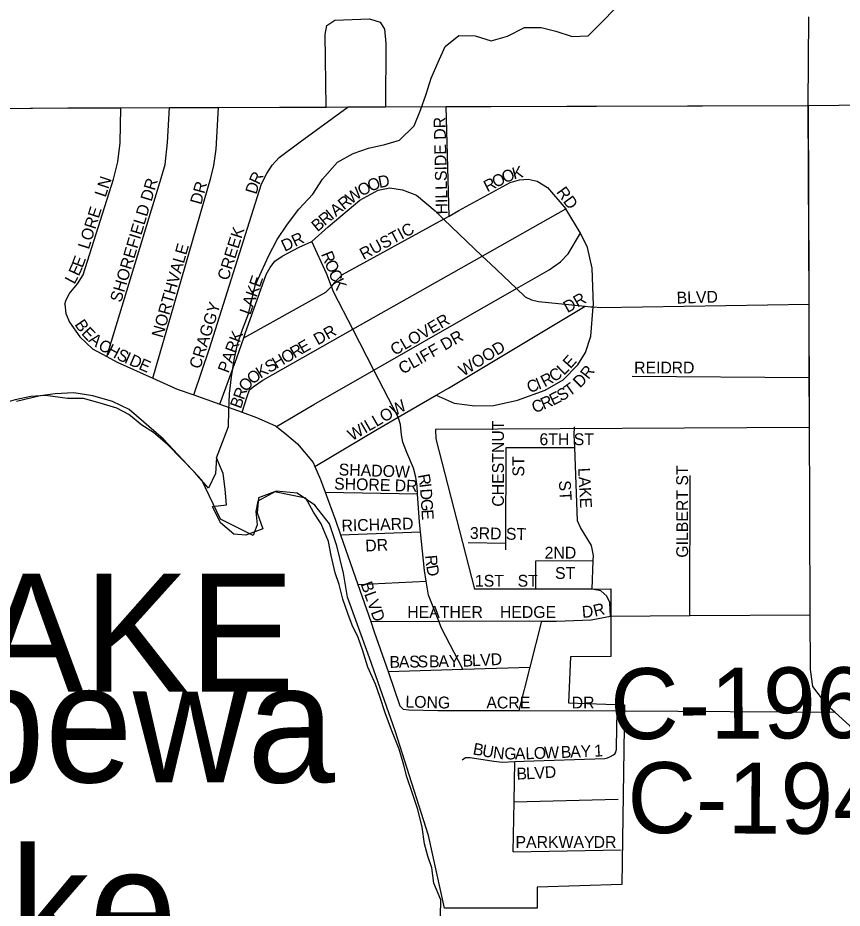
# Model space of a CAD drawing. Extents: x 1985906 to 2277390, y 930619 to 1324581.
# Drawn here: x 2131073 to 2134559, y 1117937 to 1121701 of the extents above; entities that cross this region are included whole.
import ezdxf

# ---------------------------------------------------------------- set-up
doc = ezdxf.new("R2010")
doc.units = 0
for name, color, linetype in [('GM_X_City_Street', 7, 'Continuous'), ('GM_X_City_Street_Text', 7, 'Continuous'), ('GM_X_Corporation', 7, 'Continuous'), ('GM_X_Corporation_Text', 7, 'Continuous'), ('GM_X_County_Road', 7, 'Continuous'), ('GM_X_County_Road_Text', 7, 'Continuous'), ('GM_X_Major_Lake', 7, 'Continuous'), ('GM_X_Major_Lake_Text', 7, 'Continuous'), ('GM_X_Minor_River', 7, 'Continuous'), ('GM_X_Township_Road', 7, 'Continuous'), ('GM_X_Township_Subdivision', 7, 'Continuous'), ('GM_X_Township_Subdivision_Text', 7, 'Continuous')]:
    doc.layers.add(name, color=color, linetype=linetype)

msp = doc.modelspace()

# ---------------------------------------------------------------- linework, layer by layer
at = {"layer": 'GM_X_City_Street'}
for points in [[(2131272.5, 1120490.7), (2131276.6, 1120504.7), (2131290.8, 1120534.7), (2131325.1, 1120576.5), (2131349.3, 1120614.5), (2131477.5, 1121018.5), (2131495.9, 1121092.5), (2131506.3, 1121172.6), (2131509.1, 1121320.9)], [(2131449.3, 1120269.1), (2131683.8, 1121037.3), (2131696.1, 1121081.3), (2131706.6, 1121173.4), (2131715.3, 1121321.6)], [(2131644.4, 1120177.4), (2131890, 1121024.1), (2131902.2, 1121076.1), (2131912.6, 1121146.2), (2131921.6, 1121322.3)], [(2131817.2, 1120107), (2131884.2, 1120302.8), (2132104.1, 1120998.8), (2132126.3, 1121042.7), (2132148.5, 1121078.7), (2132178.7, 1121110.6), (2132267.2, 1121176.2), (2132470.1, 1121324.1)], [(2132896.7, 1120862.9), (2132884.5, 1121325.4)], [(2132028.4, 1120347.5), (2132376, 1120540.4), (2132400.3, 1120565.1), (2132420.2, 1120590.2), (2132446.4, 1120616.1), (2132873.7, 1120850.3), (2132896.7, 1120862.9), (2132938.3, 1120885.8), (2133155.1, 1121004.7), (2133195.3, 1121016.5), (2133231.3, 1121018.3), (2133269.3, 1121010.1), (2133313.2, 1120983.8), (2133390.8, 1120893.2)], [(2132317, 1120755.1), (2132385.4, 1120816.9), (2132520.1, 1120930.3), (2132596.4, 1120971.9), (2132646.5, 1120981.6), (2132700.5, 1120973.3), (2132758.5, 1120950.9), (2132838.2, 1120884.3), (2132873.7, 1120850.3), (2133037.2, 1120693.3), (2133071.3, 1120660.6), (2133181.8, 1120556.3), (2133218.7, 1120521.5), (2133244.7, 1120509.3), (2133274.6, 1120501.1), (2133472.8, 1120481.9), (2133496.4, 1120479.7)], [(2132021.6, 1120033.4), (2132042.5, 1120100.3), (2132053.3, 1120127.8), (2132068.1, 1120140.7), (2132109.7, 1120169.3), (2132490.1, 1120384.2), (2133037.2, 1120693.3), (2133390.8, 1120893.2)], [(2132167.4, 1119972.9), (2132325.4, 1120065.9), (2132579, 1120211.1), (2133181.8, 1120556.3), (2133319.4, 1120635.1), (2133367.6, 1120668.9), (2133399.8, 1120702.8), (2133452.4, 1120790.6), (2133390.8, 1120893.2)], [(2133155.2, 1120077.7), (2133155.7, 1120077.9), (2133186.4, 1120084.9), (2133302.8, 1120126.3), (2133379, 1120169.9), (2133441.4, 1120233.7), (2133473.8, 1120285.6), (2133496.1, 1120355.6), (2133506.2, 1120478.7), (2133506.8, 1120485.8), (2133501.6, 1120642.1), (2133482.1, 1120730.3), (2133452.4, 1120790.6)], [(2131927.5, 1120067.6), (2132000.1, 1120264.1), (2132028.4, 1120347.5), (2132034.7, 1120366.1), (2132124.1, 1120616), (2132140.3, 1120646), (2132160.4, 1120671.9), (2132190.6, 1120693.8), (2132262.8, 1120731.4), (2132317, 1120755.1)], [(2132954.6, 1118946.9), (2132865.1, 1119121.1), (2132853.7, 1119149.6), (2132809.7, 1119259.7), (2132799.8, 1119318.8), (2132792.3, 1119363.9), (2132775.4, 1119528.3), (2132771.3, 1119568.4), (2132764, 1119689.1), (2132762.1, 1119720.7), (2132756.3, 1119758.8), (2132746.5, 1119796.9), (2132718.8, 1119863.2), (2132701, 1119907.4), (2132695.1, 1119937.5), (2132691.3, 1119981.6), (2132683.5, 1120007.7), (2132681.2, 1120012.2), (2132579, 1120211.1), (2132490.1, 1120384.2), (2132410, 1120540.2), (2132400.3, 1120565.1), (2132380.3, 1120616.5), (2132317, 1120755.1)], [(2131272.5, 1120490.7), (2131276.3, 1120450.6), (2131292.2, 1120414.5), (2131335.9, 1120352.1), (2131389.7, 1120301.7), (2131449.3, 1120269.1), (2131493.5, 1120245), (2131644.4, 1120177.4), (2131747.2, 1120131.3), (2131817.2, 1120107), (2131853.1, 1120094.6), (2131927.5, 1120067.6), (2132021.6, 1120033.4), (2132082.9, 1120011.1), (2132162.8, 1119976.6), (2132167.4, 1119972.9), (2132210.6, 1119938.3), (2132256.5, 1119900), (2132322.1, 1119821.4), (2132329.7, 1119804.1), (2132353.8, 1119749.1), (2132373.2, 1119696.1), (2132417, 1119576.5), (2132438.2, 1119515.4), (2132511.3, 1119304.6), (2132565.5, 1119148.5), (2132580.7, 1119104.7), (2132638.6, 1118937.6), (2132689.2, 1118791.6), (2132703.1, 1118777.5)], [(2132329.7, 1119804.1), (2132587.1, 1119958.2), (2132681.2, 1120012.2), (2132842.9, 1120105.1), (2132894.4, 1120134.7), (2133472.8, 1120481.9)], [(2133496.4, 1120479.7), (2133497.4, 1120479.6), (2133506.2, 1120478.7), (2133538.8, 1120475.6), (2134418.7, 1120490.6)], [(2133671.4, 1120186.3), (2134420, 1120180)], [(2132842.9, 1120105.1), (2132918.1, 1120072.5), (2133006.1, 1120059.9), (2133084.2, 1120061.5), (2133155.2, 1120077.7)], [(2132373.2, 1119696.1), (2132764, 1119689.1)], [(2132438.2, 1119515.4), (2132775.4, 1119528.3)], [(2132511.3, 1119304.6), (2132799.8, 1119318.8)], [(2132565.5, 1119148.5), (2132853.7, 1119149.6), (2133237.6, 1119151), (2133289.6, 1119150.7), (2133351.7, 1119150.4), (2133497.9, 1119155.5), (2133579.7, 1119171.8)], [(2133193.6, 1118771.9), (2133240.1, 1118955.3), (2133289.6, 1119150.7)], [(2132638.6, 1118937.6), (2132954.6, 1118946.9), (2133240.1, 1118955.3)], [(2132703.1, 1118777.5), (2132727.1, 1118775.3), (2132849.2, 1118772.6), (2133193.6, 1118771.9), (2133608, 1118771), (2133642.7, 1118770.9)], [(2132952.3, 1118563.6), (2132966.3, 1118573.6), (2132986.4, 1118573.5), (2133086.4, 1118558.9), (2133122.4, 1118554.7), (2133174.3, 1118556.7), (2133212.5, 1118558.1), (2133554.9, 1118570.2), (2133566.9, 1118572.4), (2133579, 1118578.1), (2133592, 1118585.1), (2133597.9, 1118589.8), (2133601.1, 1118594), (2133604.1, 1118607.2), (2133605.2, 1118618), (2133608, 1118771)], [(2133168.5, 1118175.7), (2133171.7, 1118386.1), (2133174.3, 1118556.7)], [(2133171.7, 1118386.1), (2133612.1, 1118397.6)], [(2133168.5, 1118175.7), (2133625, 1118183.1)]]:
    msp.add_lwpolyline(points, dxfattribs=at)
at = {"layer": 'GM_X_Corporation'}
msp.add_lwpolyline([(2130535, 1121313.6), (2131284.7, 1121320.1), (2134415.5, 1121330.5), (2134417.8, 1120570.3), (2134419.8, 1119968.9), (2132838.9, 1119960.6), (2132841.1, 1119920.6), (2133004.7, 1119286), (2133580.8, 1119287.5), (2133580.5, 1119001.3), (2133410.2, 1118998.9), (2133402.1, 1118804.5), (2133638.6, 1118796.9), (2133627.2, 1118036.3), (2133268.8, 1118025.3), (2133269.1, 1117937.2), (2132877, 1117937.3), (2132810, 1118244.2), (2132668.4, 1118687.2), (2132559.7, 1118994.8), (2132468, 1119251), (2132450, 1119353.1), (2132422.4, 1119468.5), (2132391.9, 1119561.7), (2132328.9, 1119640.9), (2132254.7, 1119691.4), (2132166.1, 1119699.9), (2132088.9, 1119657.3), (2132080, 1119614.1), (2132084.8, 1119556.8), (2132068.9, 1119512.9), (2131929.8, 1119581.8), (2131850.9, 1119746.1), (2131689.1, 1119920.1), (2131544.5, 1120044.8), (2131473.4, 1120078.2), (2131389.9, 1120103.3), (2131310.5, 1120115.9), (2131231.1, 1120111.7), (2131168.5, 1120103.4), (2131068.2, 1120078.3)], dxfattribs=at)
at = {"layer": 'GM_X_County_Road'}
for points in [[(2134415.4, 1121330.5), (2134418.2, 1121704.9)], [(2134415.4, 1121330.5), (2135973.6, 1121346.6), (2138096.7, 1121368.5), (2139421.7, 1121372.5), (2139532.2, 1121368.7), (2139727, 1121340.9), (2139773.1, 1121339.9), (2139819.3, 1121339), (2139853.5, 1121339.3)], [(2130494.8, 1121313.2), (2130495.5, 1121313.2), (2131284.7, 1121320.1), (2131509.1, 1121320.9), (2131715.3, 1121321.6), (2131921.6, 1121322.3), (2132376.9, 1121323.8), (2132470.1, 1121324.1), (2132627.9, 1121324.6), (2132884.5, 1121325.4), (2134415.4, 1121330.5)], [(2134420.6, 1120017.5), (2134420, 1120180), (2134418.7, 1120490.6), (2134415.4, 1121330.5)], [(2134719.5, 1116126.1), (2134719.5, 1116126.1), (2134684.2, 1116198.7), (2134678, 1116250.6), (2134678, 1116428.9), (2134636.6, 1118553.8), (2134627.9, 1118638), (2134591.3, 1118707.9), (2134527.3, 1118765.4), (2134498.3, 1118791.5), (2134435.4, 1118873.3), (2134424.8, 1118945.5), (2134423.9, 1119177.2), (2134420.6, 1120017.5), (2134420.6, 1120017.5)], [(2133579.7, 1119171.8), (2133915, 1119174), (2134423.9, 1119177.2)], [(2133642.7, 1118770.9), (2134527.3, 1118765.4)]]:
    msp.add_lwpolyline(points, dxfattribs=at)
at = {"layer": 'GM_X_Major_Lake'}
for points in [[(2131128.7, 1120099.5), (2131062.5, 1120085.3), (2131012.3, 1120071.2), (2130943.9, 1120091)], [(2132860.7, 1117902.4), (2132862.5, 1117972.6), (2132832.1, 1118042.7), (2132823.8, 1118106.8), (2132807.5, 1118156.9), (2132793.3, 1118209), (2132783, 1118279.1), (2132764.6, 1118353.3), (2132742.3, 1118421.4), (2132717.9, 1118491.5), (2132705.6, 1118541.6), (2132685.3, 1118609.7), (2132654.9, 1118685.9), (2132626.5, 1118762), (2132604.1, 1118832.1), (2132585.8, 1118884.2), (2132553.4, 1118956.3), (2132531, 1119028.4), (2132512.8, 1119080.5), (2132486.4, 1119132.6), (2132468.2, 1119182.7), (2132447.9, 1119242.8), (2132431.5, 1119304.9), (2132415.3, 1119355), (2132398.9, 1119427.1), (2132386.7, 1119487.2), (2132356.3, 1119561.4), (2132323.9, 1119611.4), (2132291.6, 1119669.5), (2132227.2, 1119683.3), (2132158.9, 1119697.2), (2132090.6, 1119670.9), (2132084.9, 1119608.8), (2132109.2, 1119540.7), (2132037, 1119514.4), (2131986.7, 1119518.3), (2131930.3, 1119566.2), (2131895.9, 1119634.3), (2131956.1, 1119642.5), (2131949.9, 1119708.7), (2131941.6, 1119774.8), (2131913.2, 1119840.9), (2131909.4, 1119774.8), (2131879.5, 1119712.5), (2131821, 1119780.5), (2131764.6, 1119838.5), (2131706.1, 1119896.5), (2131647.6, 1119948.5), (2131597.3, 1119978.5), (2131542.9, 1120024.4), (2131492.5, 1120050.4), (2131422.1, 1120072.2), (2131351.7, 1120092.1), (2131283.4, 1120091.9), (2131191, 1120103.7), (2131128.7, 1120099.5)], [(2132860.7, 1117902.4), (2132862.5, 1117972.6), (2132832.1, 1118042.7), (2132823.8, 1118106.8), (2132807.5, 1118156.9), (2132793.3, 1118209), (2132783, 1118279.1), (2132764.6, 1118353.3), (2132742.3, 1118421.4), (2132717.9, 1118491.5), (2132705.6, 1118541.6), (2132685.3, 1118609.7), (2132654.9, 1118685.9), (2132626.5, 1118762), (2132604.1, 1118832.1), (2132585.8, 1118884.2), (2132553.4, 1118956.3), (2132531, 1119028.4), (2132512.8, 1119080.5), (2132486.4, 1119132.6), (2132468.2, 1119182.7), (2132447.9, 1119242.8), (2132431.5, 1119304.9), (2132415.3, 1119355), (2132398.9, 1119427.1), (2132386.7, 1119487.2), (2132356.3, 1119561.4), (2132323.9, 1119611.4), (2132291.6, 1119669.5), (2132227.2, 1119683.3), (2132158.9, 1119697.2), (2132090.6, 1119670.9), (2132084.9, 1119608.8), (2132109.2, 1119540.7), (2132037, 1119514.4), (2131986.7, 1119518.3), (2131930.3, 1119566.2), (2131895.9, 1119634.3), (2131956.1, 1119642.5), (2131949.9, 1119708.7), (2131941.6, 1119774.8), (2131913.2, 1119840.9), (2131909.4, 1119774.8), (2131879.5, 1119712.5), (2131821, 1119780.5), (2131764.6, 1119838.5), (2131706.1, 1119896.5), (2131647.6, 1119948.5), (2131597.3, 1119978.5), (2131542.9, 1120024.4), (2131492.5, 1120050.4), (2131422.1, 1120072.2), (2131351.7, 1120092.1), (2131283.4, 1120091.9), (2131191, 1120103.7), (2131128.7, 1120099.5)]]:
    msp.add_lwpolyline(points, dxfattribs=at)
at = {"layer": 'GM_X_Minor_River'}
msp.add_lwpolyline([(2131913, 1119841.2), (2131963.8, 1119973.1), (2131965, 1120041.3), (2131968.2, 1120111.4), (2131977.5, 1120183.5), (2131988.8, 1120255.5), (2132002, 1120321.4), (2132023.1, 1120383.2), (2132048.4, 1120449), (2132063.6, 1120514.9), (2132076.6, 1120568.8), (2132103.7, 1120628.5), (2132135, 1120696.1), (2132170.3, 1120763.7), (2132213.7, 1120829.1), (2132261, 1120892.4), (2132320.3, 1120955.6), (2132361.6, 1121019), (2132425.1, 1121090.1), (2132492, 1121127), (2132556.7, 1121149.9), (2132625.3, 1121164.7), (2132687.9, 1121183.6), (2132749.2, 1121244.7), (2132776.5, 1121310.4), (2132799.7, 1121378.2), (2132821, 1121446), (2132850.3, 1121513.7), (2132879.6, 1121579.3), (2132938.6, 1121626.4), (2133006.9, 1121625.2), (2133074.8, 1121603.9), (2133143.5, 1121622.7), (2133216.4, 1121659.5), (2133286.8, 1121660.2), (2133348.8, 1121645.1), (2133416.7, 1121621.8), (2133485, 1121624.5), (2133540.2, 1121679.7), (2133601.6, 1121742.8)], dxfattribs=at)
at = {"layer": 'GM_X_Township_Road'}
msp.add_lwpolyline([(2132376.9, 1121323.8), (2132372.3, 1121630.6), (2132380.2, 1121668.7), (2132414.3, 1121690.8), (2132560.9, 1121697.1), (2132605.1, 1121683.1), (2132623.2, 1121653), (2132629.4, 1121592.9), (2132627.9, 1121324.6)], dxfattribs=at)
at = {"layer": 'GM_X_Township_Subdivision'}
for points in [[(2133501.2, 1119286), (2133506.1, 1119407.3), (2133506.9, 1119428.4), (2133498.8, 1119470.5), (2133452.5, 1119546.6), (2133440.4, 1119574.7), (2133427.9, 1119883.7), (2133425.6, 1119939.7), (2133427.6, 1119971.7)], [(2133137.1, 1119451.8), (2133137.2, 1119479.8), (2133137.6, 1119884.6)], [(2133137.6, 1119884.6), (2133427.9, 1119883.7)], [(2133915, 1119174), (2133915.8, 1119765.9)], [(2132978.1, 1119482.6), (2133137.2, 1119479.8)], [(2133263.2, 1119286), (2133263, 1119405.7), (2133506.1, 1119407.3)], [(2133579.7, 1119171.8), (2133575.9, 1119228.7), (2133564.1, 1119256.3), (2133538.5, 1119278), (2133501.2, 1119286), (2133263.2, 1119286), (2133004.7, 1119286)]]:
    msp.add_lwpolyline(points, dxfattribs=at)

# ---------------------------------------------------------------- texts
at = {"layer": 'GM_X_City_Street_Text'}
for s, rotation, p in [('HILLSIDE DR', 91.3497, (2132891.1, 1120870.3)), ('K', 14.1317, (2133170.6, 1121017.4)), ('R', 64.9449, (2132093.9, 1120992.2)), ('D', 11.0828, (2132602.1, 1120980.9)), ('O', 27.2983, (2133094, 1120980.6)), ('O', 23.7095, (2133132.4, 1121000.4)), ('LN', 71.5614, (2131444, 1120939.5)), ('SHOREFIELD DR', 73.2507, (2131509.9, 1120494.8)), ('DR', 74.4821, (2131848.7, 1120908.2)), ('D', 72.968, (2132081.7, 1120951.8)), ('O', 28.3348, (2132526.6, 1120944.4)), ('O', 22.7308, (2132564.1, 1120964.7)), ('R', 27.3253, (2133058.9, 1120962.4)), ('W', 36.685, (2132482.3, 1120911.2)), ('RD', 306.2589, (2133348.1, 1120964.1)), ('R', 39.4449, (2132452.2, 1120886.5)), ('LORE', 72.3509, (2131373.5, 1120719.4)), ('I', 39.4586, (2132401.3, 1120844.5)), ('A', 39.4586, (2132418.3, 1120858.5)), ('B', 39.4449, (2132340.1, 1120794.2)), ('R', 39.4663, (2132370.7, 1120819.4)), ('CREEK', 72.5234, (2131963.1, 1120587.4)), ('RUSTIC', 28.1408, (2132535.3, 1120676.5)), ('DR', 25.1955, (2132201.7, 1120711.4)), ('NORTHVALE', 74.1466, (2131685.8, 1120345.1)), ('E', 69.308, (2131346.8, 1120641)), ('R', 291.8465, (2132354.8, 1120702.4)), ('E', 65.6951, (2131331.1, 1120605.9)), ('O', 291.866, (2132369.6, 1120665.7)), ('C', 291.8465, (2132386, 1120624.8)), ('L', 61.6752, (2131312.7, 1120571.5)), ('E', 70.6494, (2132097, 1120558.5)), ('K', 296.7359, (2132402.6, 1120583.8)), ('K', 70.6599, (2132082.5, 1120516.9)), ('BLVD', 1.5065, (2133859.5, 1120492.7)), ('A', 70.6457, (2132067.9, 1120475.4)), ('DR', 29.3668, (2133397.5, 1120451.9)), ('CRAGGY', 72.4728, (2131844.3, 1120213.4)), ('L', 70.6494, (2132056.2, 1120442.2)), ('CLOVER', 30.2562, (2132667, 1120271.5)), ('B', 304.3772, (2131311.5, 1120404.4)), ('E', 313.4469, (2131339.2, 1120365)), ('DR', 29.3565, (2132341.5, 1120315.5)), ('A', 322.0216, (2131369.5, 1120334)), ('PARK', 69.6228, (2131963.9, 1120196)), ('CLIFF DR', 29.513, (2132700.6, 1120192.3)), ('C', 328.1868, (2131409, 1120303.6)), ('H', 332.2213, (2131446, 1120280.8)), ('R', 30.1184, (2132242.9, 1120259.8)), ('E', 30.1109, (2132277.2, 1120279.6)), ('WOOD', 31.8917, (2132957.1, 1120183.3)), ('S', 335.3553, (2131487.6, 1120259)), ('I', 336.1347, (2131520.2, 1120244)), ('O', 30.111, (2132204.8, 1120237.7)), ('D', 336.3647, (2131540.6, 1120235)), ('E', 336.3691, (2131580.9, 1120217.3)), ('S', 30.1719, (2132136.3, 1120197.9)), ('H', 30.1054, (2132166.8, 1120215.6)), ('E', 48.6455, (2133410.1, 1120214.7)), ('REID', 0, (2133679.3, 1120197.3)), ('RD', 0, (2133837.7, 1120197.3)), ('O', 37.7005, (2132065.7, 1120148.7)), ('K', 32.017, (2132099.4, 1120174.8)), ('C', 32.0165, (2133339.2, 1120159.1)), ('L', 43.963, (2133381.7, 1120187.1)), ('R', 51.8481, (2133486, 1120169.5)), ('O', 51.6746, (2132040.7, 1120116.4)), ('C', 19.925, (2133236.2, 1120113.8)), ('I', 22.1932, (2133275.4, 1120128.1)), ('R', 27.7605, (2133300.6, 1120138.6)), ('D', 45.0788, (2133450.6, 1120133.5)), ('R', 70.0957, (2132029.2, 1120082.9)), ('S', 29.4151, (2133369.8, 1120077.7)), ('T', 35.5097, (2133405.4, 1120098.1)), ('B', 70.0978, (2132015.8, 1120045.6)), ('R', 22.8322, (2133296.3, 1120043.6)), ('E', 27.0222, (2133336.4, 1120060.6)), ('WILLOW', 30.1116, (2132486.6, 1119910.7)), ('C', 20.7237, (2133257.4, 1120028.8)), ('SHADOW', 358.1232, (2132429.6, 1119766.7)), ('SHORE DR', 358.3163, (2132410.2, 1119707.1)), ('R', 280.3049, (2132764.5, 1119768.2)), ('I', 276.9678, (2132771.4, 1119730)), ('D', 273.9595, (2132774.1, 1119708.9)), ('G', 273.5872, (2132777.1, 1119665.1)), ('E', 273.5815, (2132779.8, 1119621.1)), ('RICHARD', 1.8173, (2132442.6, 1119529.1)), ('DR', 3.011, (2132543.7, 1119444.2)), ('R', 275.1065, (2132795.5, 1119427.8)), ('D', 280.4958, (2132799.7, 1119383.3)), ('BLVD', 289.8563, (2132522.1, 1119307.3)), ('HEATHER', 0, (2132720.1, 1119163.9)), ('HEDGE', 0, (2133111.7, 1119163.9)), ('D', 4.3534, (2133460.3, 1119164)), ('R', 13.963, (2133513.1, 1119168.7)), ('B', 0.8257, (2132645.2, 1118952.7)), ('A', 0.8154, (2132684.7, 1118953.3)), ('S', 0.8196, (2132728.7, 1118954)), ('S', 0.8196, (2132763.9, 1118954.5)), ('B', 0.8253, (2132812.3, 1118955.1)), ('A', 0.8261, (2132851.9, 1118955.7)), ('Y', 0.9054, (2132896, 1118956.4)), ('B', 2.5586, (2132954.8, 1118957.5)), ('L', 2.9287, (2132994.7, 1118959.3)), ('V', 2.9301, (2133029.8, 1118961.1)), ('D', 2.9301, (2133073.8, 1118963.3)), ('LONG', 358.5313, (2132711.7, 1118785.5)), ('ACRE', 0, (2133054.5, 1118781.2)), ('DR', 0, (2133415.3, 1118781.1)), ('B', 349.352, (2132994.7, 1118587.4)), ('U', 349.3374, (2133033.6, 1118580.1)), ('Y', 2.2249, (2133453.8, 1118575)), ('1', 2.2425, (2133511, 1118577.2)), ('N', 353.096, (2133080.4, 1118571.4)), ('G', 359.8578, (2133130.5, 1118565.7)), ('A', 0.5787, (2133175.2, 1118565.6)), ('L', 1.9022, (2133220.4, 1118566.1)), ('O', 2.2474, (2133255.9, 1118567.2)), ('W', 2.22, (2133299.9, 1118569)), ('B', 2.2343, (2133370.2, 1118571.7)), ('A', 2.2303, (2133409.8, 1118573.3)), ('B', 1.3599, (2133182.4, 1118480.5)), ('L', 2.9896, (2133223.5, 1118481.5)), ('V', 3.4244, (2133259.1, 1118483.3)), ('D', 3.5852, (2133303.2, 1118486)), ('PARKWAY', 0, (2133177.7, 1118191.5)), ('DR', 0, (2133507.7, 1118191.5))]:
    msp.add_text(s, height=50, rotation=rotation, dxfattribs=at).set_placement(p)
at = {"layer": 'GM_X_Corporation_Text'}
msp.add_text('CHIPPEWA LAKE', height=500, rotation=0, dxfattribs=at).set_placement((2126782, 1118851.6))
at = {"layer": 'GM_X_County_Road_Text'}
for s, rotation, p in [('C-196', 0.274, (2133578.5, 1118650.9)), ('C-194', 359.7247, (2133650.4, 1118254.9))]:
    msp.add_text(s, height=300, rotation=rotation, dxfattribs=at).set_placement(p)
at = {"layer": 'GM_X_Major_Lake_Text'}
for s, rotation, p in [('Chippewa', 359.9636, (2129440, 1118470.1)), ('Lake', 359.9641, (2130296.7, 1117692.6))]:
    msp.add_text(s, height=500.2, rotation=rotation, dxfattribs=at).set_placement(p)
at = {"layer": 'GM_X_Township_Subdivision_Text'}
for s, rotation, p in [('CHESTNUT', 90, (2133128.7, 1119634.1)), ('6TH ST', 0, (2133278.9, 1119894.3)), ('ST', 90, (2133214.7, 1119761.7)), ('LAKE', 273.0925, (2133442.3, 1119797.4)), ('GILBERT ST', 90, (2133907.5, 1119418.5)), ('ST', 273.5738, (2133360.8, 1119743.8)), ('3RD ST', 358.7554, (2132984.3, 1119498.3)), ('2ND', 0, (2133300.9, 1119414.7)), ('ST', 0, (2133344.9, 1119328.7)), ('1ST', 0, (2133006.1, 1119296)), ('ST', 0, (2133186.5, 1119296))]:
    msp.add_text(s, height=50, rotation=rotation, dxfattribs=at).set_placement(p)

doc.saveas('drawing.dxf')
